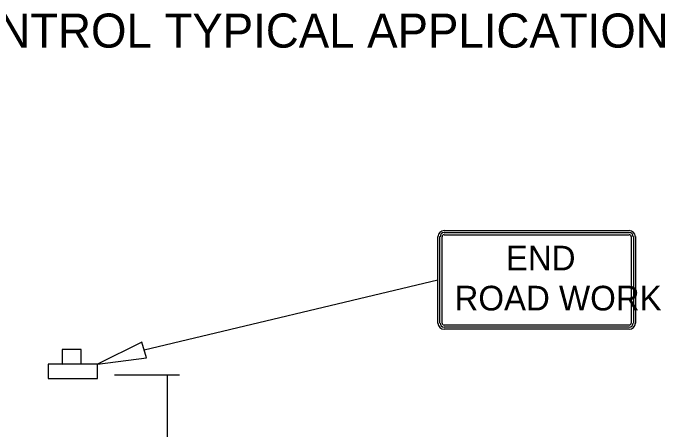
# Model space of a CAD drawing. Extents: x 1531.2 to 1543.2, y 1529.6 to 1539.7.
# Drawn here: x 1534.547 to 1536.509, y 1538.427 to 1539.682 of the extents above; entities that cross this region are included whole.
import ezdxf

# ---------------------------------------------------------------- set-up
doc = ezdxf.new("R2010")
doc.units = 0
for name, color, linetype in [('DETL-DIMS', 7, 'Continuous'), ('DETL-LINE', 7, 'Continuous'), ('DETL-TITL', 7, 'Continuous'), ('SIGN-FACE_P', 7, 'Continuous'), ('USER-BORD', 7, 'Continuous')]:
    doc.layers.add(name, color=color, linetype=linetype)

# ---------------------------------------------------------------- blocks, each defined once
blk = doc.blocks.new('SIGN13')
at = {"layer": 'USER-BORD'}
for points in [[(-0.0134, 0.0182), (0.011, 0.0189), (0.011, 0.0371), (-0.0134, 0.0371)], [(-0.0314, 0.0182), (-0.0314, 0), (0.032, 0), (0.032, 0.0182)]]:
    blk.add_lwpolyline(points, close=True, dxfattribs=at)

msp = doc.modelspace()

# ---------------------------------------------------------------- linework, layer by layer
at = {"layer": 'DETL-DIMS'}
for p, q in [((1534.9414, 1538.6681), (1535.8254, 1538.8792)), ((1534.8524, 1538.5928), (1535.0481, 1538.5928)), ((1535.0115, 1538.0995), (1535.0115, 1538.5928))]:
    msp.add_line(p, q, dxfattribs=at)
msp.add_lwpolyline([(1534.9486, 1538.6446), (1534.9342, 1538.6917), (1534.8006, 1538.625)], close=True, dxfattribs=at)
at = {"layer": 'SIGN-FACE_P'}
for p, q in [((1535.8439, 1539.0277), (1536.401, 1539.0277)), ((1535.8439, 1539.0277), (1536.401, 1539.0277)), ((1535.8439, 1539.0217), (1536.401, 1539.0217)), ((1535.8439, 1539.0152), (1536.401, 1539.0152)), ((1535.8254, 1538.7491), (1535.8254, 1539.0093)), ((1535.8314, 1538.7491), (1535.8314, 1539.0093)), ((1535.8379, 1538.7491), (1535.8379, 1539.0093)), ((1536.4069, 1539.0093), (1536.4069, 1538.7491)), ((1536.4135, 1539.0093), (1536.4135, 1538.7491)), ((1536.4194, 1539.0093), (1536.4194, 1538.7491)), ((1536.401, 1538.7432), (1535.8439, 1538.7432)), ((1536.401, 1538.7366), (1535.8439, 1538.7366)), ((1536.401, 1538.7307), (1535.8439, 1538.7307))]:
    msp.add_line(p, q, dxfattribs=at)
for centre, radius, start, end in [((1535.844, 1539.0091), 0.0186, 90, 180), ((1535.844, 1539.0091), 0.0124, 90, 180), ((1535.844, 1539.0091), 0.00619, 90, 180), ((1536.4008, 1539.0091), 0.0186, 0, 90), ((1536.4008, 1539.0091), 0.0124, 0, 90), ((1536.4008, 1539.0091), 0.00619, 0, 90), ((1535.844, 1538.7493), 0.0186, 180, 270), ((1535.844, 1538.7493), 0.0124, 180, 270), ((1535.844, 1538.7493), 0.00619, 180, 270), ((1536.4008, 1538.7493), 0.0186, 270, 0), ((1536.4008, 1538.7493), 0.0124, 270, 0), ((1536.4008, 1538.7493), 0.00619, 270, 0)]:
    msp.add_arc(centre, radius, start, end, dxfattribs=at)

# ---------------------------------------------------------------- block references
at = {"layer": 'DETL-LINE', "xscale": 2.33340420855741, "yscale": 2.33340420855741}
msp.add_blockref('SIGN13', (1534.7259, 1538.5825), dxfattribs=at)

# ---------------------------------------------------------------- texts
at = {"layer": 'DETL-TITL'}
msp.add_text('TEMPORARY TRAFFIC CONTROL TYPICAL APPLICATION', height=0.1026, dxfattribs=at).set_placement((1532.7691, 1539.5783))
at = {"layer": 'SIGN-FACE_P'}
for s, p in [('END', (1536.0298, 1538.9077)), ('ROAD WORK', (1535.8753, 1538.7871))]:
    msp.add_text(s, height=0.07424, dxfattribs=at).set_placement(p)

doc.saveas('drawing.dxf')
